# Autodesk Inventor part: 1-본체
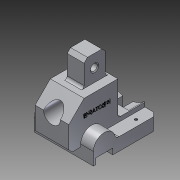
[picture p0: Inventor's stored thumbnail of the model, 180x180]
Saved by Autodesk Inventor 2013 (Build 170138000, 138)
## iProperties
Created: 2016-11
Part Number: 1-본체
Material: 알루미늄 6061
Document SubType Name: Modeling
Designer: cad22
Density: 2.40731 g/cm^3
Mass: 420.015 g
Surface Area: 320.137 cm^2
Volume: 174.475 cm^3
Author: cad22
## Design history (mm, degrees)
sketch "스케치1"
  geometry: L1 (-29, 6)-(-11, 24); L2 (-11, 24)-(29, 24); L3 (29, 24)-(29, -16); L4 (-29, 6)-(-29, -24); L5 (-29, -24)-(29, -24); L6 (61, -16)-(29, -16); L7 (29, -36)-(61, -36); L8 (61, -36)-(61, -16); L9 (29, -36)-(29, -24); 3 further points
  constraints: 18 end point, 4 perpendicular, 2 parallel, 1 horizontal, 1 horizontal alignment, 1 midpoint, 1 point on line, 1 vertical alignment
  dimensions: "d0" = 45 deg angle of L2 L1; "d1" = 18 distance from line of L1.end L4; "d3" = 58 distance between parallel lines of L3 L4; "d125" = 48 distance between parallel lines of L5 L2; "d151" = 60 distance between parallel lines of L2 L7; "d152" = 20 distance between parallel lines of L6 L7; "d153" = 90 distance between parallel lines of L4 L8; "d154" = 32 distance between parallel lines of L8 L9; "d155" = 36 distance from line of point (0, 0) L7
extrude "돌출1" new body sketch "스케치1" stored distance "d8" = 40; taper "d9" = 0 deg
chamfer "모따기1" distance "d47" = 4; stored, may be unused: second distance "d48" = 2, angle "d49" = 45 deg
sketch "스케치5"
  geometry: L1 (-15, -21)-(-15, -36); L2 (-15, -36)-(-12, -36); L3 (-12, -29)-(-12, -36); L4 (-12, -29)-(8, -29); L5 (8, -29)-(8, -36); L6 (8, -36)-(61, -36); L7 (61, -36)-(61, -21); L8 (61, -21)-(11, -21); L9 (29, -16)-(61, -16) reference; L10 (-11, 24)-(29, 24) reference; A1 r 13 centre (-2, -21) between (11, -21) and (-15, -21); 1 further point
  constraints: 16 end point, 6 perpendicular, 2 point on circle, 1 centre point, 1 parallel, 1 tangent, 1 vertical
  dimensions: "d38" = 20 distance of L3.start L4.end; "d39" = 3 distance of L1.end L2.end; "d40" = 7 distance of L3.start L2.end; "d41" = 7 distance of L4.end L5.end; "d42" = 63 distance from line of L7 A1.centre; "d43" = 13 radius of A1; "d134" = 60 distance between parallel lines of L10 L6; "d135" = 15 distance between parallel lines of L6 L8; "d167" = 0 distance from line of L9.end L7; "d168" = 5 distance from line of A1.centre L9
extrude "돌출2" join sketch "스케치5" stored distance "d45" = 70; taper "d46" = 0 deg
sketch "스케치7"
  geometry: L1 (-11, 24)-(29, 24) reference; L2 (29, 24)-(29, -16) reference; L3 (-1, 24)-(-1, 54); L4 (-1, 54)-(24, 54); L5 (24, 54)-(24, 24); L6 (61, -36)-(8, -36) reference; 2 further points
  constraints: 6 end point, 2 perpendicular, 2 point on line, 1 midpoint, 1 parallel
  dimensions: "d61" = 5 distance between parallel lines of L5 L2; "d62" = 90 distance between parallel lines of L6 L4; "d63" = 25 distance of L3.end L4.end
extrude "돌출3" join sketch "스케치7" stored distance "d65" = 20; taper "d66" = 0 deg
sketch "스케치8"
  geometry: L1 (-54, -1)-(-24, -1) reference; L2 (-24, 24)-(-54, 24) reference; 3 further points
  constraints: 1 midpoint, 1 vertical alignment
  dimensions: "d71" = 12.5 distance from line of L1 point (-39, 11.5)
hole "구멍2" sketch "스케치8" at (-39, 11.5) diameter "d72" = 8; stored, may be unused: countersink angle "d76" = 90 deg, drill point angle "d78" = 118 deg; dims "d73" = 6, "d74" = 28, "d75" = 7, "d77" = 8
chamfer "모따기4" distance "d79" = 1; stored, may be unused: second distance "d80" = 2, angle "d81" = 45 deg
sketch "스케치11"
  geometry: L1 (-55, 50)-(15, 50) reference; 4 further points
  constraints: 1 point on line, 1 vertical alignment
  dimensions: "d93" = 18 distance from line of point (7.5, 32) L1
hole "구멍3" sketch "스케치11" at (7.5, 32) diameter "d94" = 3.242; stored, may be unused: countersink angle "d98" = 90 deg, drill point angle "d100" = 118 deg; dims "d95" = 6, "d96" = 28, "d97" = 7, "d99" = 8
chamfer "모따기5" distance "d101" = 5; stored, may be unused: second distance "d102" = 2, angle "d103" = 45 deg
node "작업 평면1"
sketch "스케치12"
  geometry: L1 (-24, 29)-(-24, -11) reference; L2 (16, 29)-(-24, 29) reference; 2 further points
  constraints: 1 other
  dimensions: "d105" = 18 distance from line of L1 point (-6, 4); "d106" = 25 distance from line of L2 point (-6, 4)
feature "엠보싱1" sketch "스케치12" dims "d0" = 45 deg, "d1" = 18, "d3" = 58, "d107" = 0.5, "d108" = 0, "d125" = 48, "d151" = 60, "d152" = 20, "d153" = 90, "d154" = 32, "d155" = 36
fillet "모깎기1" dims "d109" = 5
fillet "모깎기2" dims "d110" = 3
chamfer "모따기7" distance "d136" = 4; stored, may be unused: second distance "d137" = 2, angle "d138" = 45 deg
sketch "스케치14"
  geometry: L1 (40, 37)-(40, 0) reference; L2 (-15, 60)-(55, 60) reference; 2 further points
  dimensions: "d165" = 42 distance from line of L2 point (20, 18); "d166" = 20 distance from line of point (20, 18) L1
hole "구멍6" sketch "스케치14" at (20, 18) diameter "d141" = 20; stored, may be unused: countersink angle "d145" = 90 deg, drill point angle "d147" = 118 deg; dims "d142" = 6, "d143" = 29, "d144" = 7, "d146" = 8
chamfer "모따기8" distance "d148" = 1; stored, may be unused: second distance "d149" = 2, angle "d150" = 45 deg
sketch "스케치15"
  geometry: C1 r 14.5 at (20, -22) reference; C2 r 11 at (20, -22) reference; C3 r 29 at (20, -22); 1 further point
  constraints: 1 centre point, 1 coincident
  dimensions: "d156" = 58 diameter of C3
extrude "돌출7" cut sketch "스케치15" distance "d158" = 18; taper "d159" = 0 deg
sketch "스케치16"
  geometry: L1 (10, 20)-(-50, 20) reference; L2 (-26, 0)-(-14, 0); L3 (-14, 0)-(-14, 20); L4 (-14, 20)-(-26, 20); L5 (-26, 20)-(-26, 0); 2 further points
  constraints: 8 end point, 2 midpoint, 2 parallel, 1 horizontal, 1 perpendicular
  dimensions: "d160" = 12 distance of L3.end L4.end; "d162" = 20 distance between parallel lines of L2 L4
extrude "돌출8" cut sketch "스케치16" distance "d163" = 18; taper "d164" = 0 deg
node "솔리드1"
mirror "대칭1"
node "투영된 루프1"
other parameters: "d104" = 8
